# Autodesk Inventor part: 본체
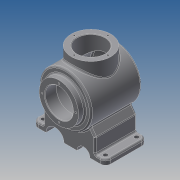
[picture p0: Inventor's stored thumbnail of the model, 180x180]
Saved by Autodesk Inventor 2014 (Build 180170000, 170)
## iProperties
Created: 2018-08
Part Number: 본체
Material: Generic
Document SubType Name: Modeling
Designer: kb542
Density: 1 g/cm^3
Appearance: Default
Author: kb542
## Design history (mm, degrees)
sketch "스케치1"
  geometry: L1 (-60, 0)-(60, 0); L2 (-60, 27)-(-60, 38); L3 (-60, 38)-(-48, 38); L4 (-48, 38)-(-48, 50); L5 (-60, 27)-(-38, 27); L6 (-38, 27)-(-38, 40); L7 (-38, 40)-(42.163, 40); L8 (-48, 50)-(48.671, 50); A1 r 116 centre (-56, 0) between (60, 0) and (48.671, 50); A2 r 106 centre (-56, 0) between (50, 0) and (42.163, 40); 2 further points
  constraints: 16 end point, 4 perpendicular, 4 point on circle, 2 centre point, 2 parallel, 1 coincident, 1 concentric, 1 horizontal, 1 horizontal alignment, 1 midpoint, 1 point on line, 1 vertical alignment
  dimensions: "d0" = 10 radial gap between concentric circles of A1 A2; "d2" = 12 distance of L2.end L3.end; "d4" = 54 diameter of L5 L1; "d5" = 76 diameter of L3 L1; "d6" = 80 diameter of L7 L1; "d7" = 100 diameter of L8 L1; "d8" = 116 radius of A1; "d9" = 22 distance of L2.start L5.end; "d10" = 108 distance from line of L1.end L4
revolve "회전1" sketch "스케치1" stored, may be unused: angle "d11" = 90 deg
node "작업 평면1"
sketch "스케치3"
  geometry: L1 (-50, -43.437)-(-50, -72); L2 (-50, -72)-(-70, -72); L3 (-70, -72)-(-70, -82); L4 (0, 0)-(0, -82); L5 (-70, -82)-(0, -82); L6 (70, -82)-(0, -82); L7 (50, -72)-(70, -72); L8 (70, -72)-(70, -82); L9 (-70, -72)-(-50, -43.437); L10 (70, -72)-(50, -43.437); L11 (50, -43.437)-(50, -72); L12 (-50, -43.437)-(-40.304, -29.59); L13 (50, -43.437)-(40.304, -29.59); C1 r 12.5 at (27.5, -82); C2 r 17.5 at (-27.5, -82); A1 r 50 centre (0, 0) between (-40.304, -29.59) and (40.304, -29.59); 1 further point
  constraints: 26 end point, 5 symmetric about line, 3 centre point, 3 perpendicular, 2 point on circle, 2 point on line, 1 parallel, 1 vertical, 3 other
  dimensions: "d14" = 20 distance between parallel lines of L3 L1; "d15" = 25 diameter of C1; "d16" = 35 diameter of C2; "d17" = 27.5 distance of C2.centre L4.end; "d18" = 27.5 distance of C1.centre L4.end; "d19" = 82 distance from line of L6 point (0, 0); "d21" = 10 distance between parallel lines of L6 L7; "d22" = 140 distance between parallel lines of L8 L3; "d25" = 35 deg angle of L3 L12; "d26" = 35 deg angle of L3 L9
extrude "돌출1" join sketch "스케치3" distance "d27" = 80; taper "d28" = 0 deg
extrude "돌출2" cut sketch "스케치3" stored distance "d29" = 80; taper "d30" = 0 deg
node "작업 평면2"
sketch "스케치4"
  geometry: L1 (-100, 32)-(-100, 108) reference; C1 r 38 at (-38, 70); 1 further point
  constraints: 1 centre point, 1 horizontal alignment
  dimensions: "d32" = 62 distance from line of C1.centre L1; "d33" = 76 diameter of C1
extrude "돌출3" join sketch "스케치4" stored distance "d34" = 80; taper "d35" = 0 deg
sketch "스케치5"
  geometry: C1 r 38 at (0, 0) reference; C2 r 27 at (0, 0); 1 further point
  constraints: 1 centre point, 1 coincident
  dimensions: "d36" = 54 diameter of C2
extrude "돌출4" cut sketch "스케치5" stored distance "d37" = 80; taper "d38" = 0 deg
sketch "스케치6"
  geometry: C1 r 27 at (0, 0) reference; 2 further points
  constraints: 1 horizontal alignment
  dimensions: "d39" = 32.5 distance of C1.centre point (-32.5, 0)
hole "구멍1" sketch "스케치6" at (-32.5, 0) diameter "d40" = 3.242; stored, may be unused: countersink angle "d44" = 90 deg, drill point angle "d46" = 118 deg; dims "d41" = 8, "d42" = 4, "d43" = 2, "d45" = 10
sketch "스케치7"
  geometry: C1 r 38 at (0, 0) reference; 1 further point
  constraints: 1 vertical alignment
  dimensions: "d50" = 32.5 distance of C1.centre point (0, 32.5)
hole "구멍2" sketch "스케치7" at (0, 32.5) diameter "d51" = 3.242; stored, may be unused: countersink angle "d55" = 90 deg, drill point angle "d57" = 118 deg; dims "d52" = 8, "d53" = 4, "d54" = 2, "d56" = 10
fillet "모깎기1" dims "d61" = 10
sketch "스케치8"
  geometry: L1 (70, -120)-(10, -120) reference; L2 (80, -110)-(80, -100) reference; L3 (80, -100)-(0, -100) reference; L4 (0, -110)-(0, -100) reference; A1 r 10 centre (10, 10) between (10, 20) and (0, 10) reference; A2 r 10 centre (70, 10) between (80, 10) and (70, 20) reference; A3 r 10 centre (10, -110) between (0, -110) and (10, -120) reference; A4 r 10 centre (70, -110) between (70, -120) and (80, -110) reference; 5 further points
  constraints: 4 coincident
hole "구멍3" sketch "스케치8" at (10, 10), (70, 10), (70, -110), (10, -110) diameter "d62" = 8; stored, may be unused: countersink angle "d66" = 90 deg, drill point angle "d68" = 118 deg; dims "d63" = 8, "d64" = 4, "d65" = 2, "d67" = 10
node "작업 평면3"
sketch "스케치9"
  geometry: C1 r 32.5 at (0, 0); 1 further point
  constraints: 1 centre point, 1 coincident, 1 other
  dimensions: "d69" = 65 diameter of C1
feature "엠보싱1" sketch "스케치9" dims "d0" = 10, "d2" = 12, "d4" = 54, "d5" = 76, "d6" = 80, "d7" = 100, "d8" = 116, "d9" = 22, "d10" = 108, "d70" = 0.5, "d71" = 0
fillet "모깎기2" dims "d72" = 3
fillet "모깎기3" dims "d73" = 3
fillet "모깎기4" dims "d74" = 3
fillet "모깎기5" dims "d75" = 3
fillet "모깎기6" dims "d76" = 3
chamfer "모따기1" distance "d77" = 1; stored, may be unused: second distance "d78" = 2, angle "d79" = 45 deg
fillet "모깎기7" dims "d80" = 3
node "솔리드1"
pattern_circular "원형 패턴1" dims angle "d48" = 360 deg
pattern_circular "원형 패턴2" dims angle "d59" = 360 deg
node "투영된 루프1"
other parameters: "d12" = -8, "d31" = -147
